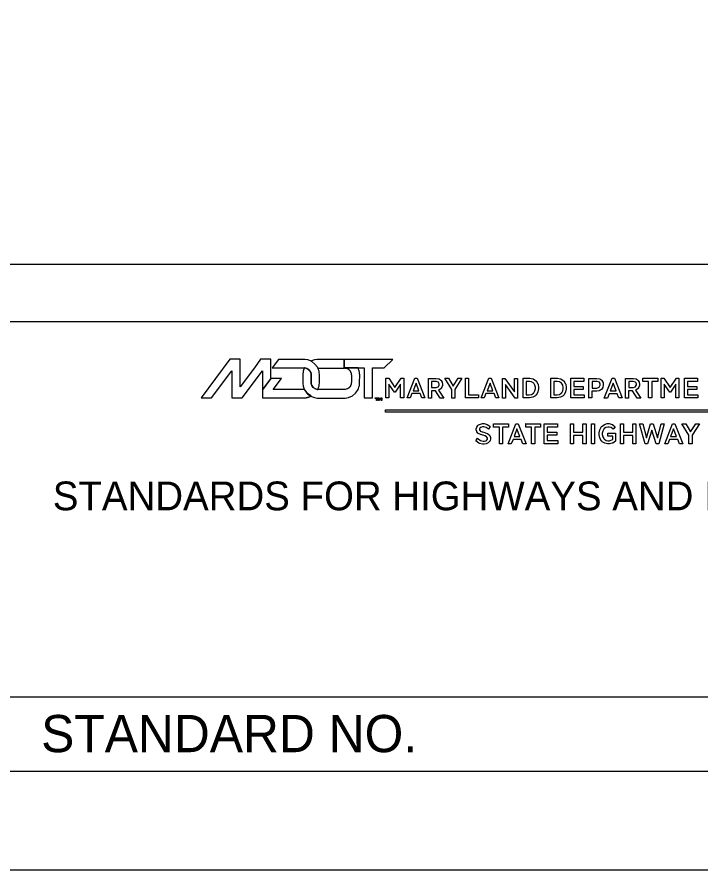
# Model space of a CAD drawing. Extents: x -0.5 to 19.9, y 5.2 to 17.3.
# Drawn here: x 15.428 to 17.634, y 5.667 to 8.417 of the extents above; entities that cross this region are included whole.
import ezdxf

# ---------------------------------------------------------------- set-up
doc = ezdxf.new("R2010")
doc.units = 0
for name, color, linetype in [('BORD-LINE', 7, 'Continuous'), ('MSHA-LOGO', 7, 'Continuous'), ('TTLB-TEXT', 7, 'Continuous'), ('USER-CLIP', 7, 'Continuous')]:
    doc.layers.add(name, color=color, linetype=linetype)

msp = doc.modelspace()

# ---------------------------------------------------------------- linework, layer by layer
at = {"layer": 'BORD-LINE'}
for p, q in [((19.6208, 7.6193), (12.2466, 7.6193)), ((19.6208, 7.4352), (15.1479, 7.4352)), ((15.1479, 6.2262), (19.6208, 6.2262))]:
    msp.add_line(p, q, dxfattribs=at)
msp.add_lwpolyline([(12.2466, 16.3375), (19.6208, 16.3375), (19.6208, 5.9844), (12.2466, 5.9844)], close=True, dxfattribs=at)
at = {"layer": 'MSHA-LOGO'}
for points in [[(16.2199, 7.2152), (16.247, 7.2513), (16.247, 7.314), (16.214, 7.314), (16.1936, 7.2866), (16.1478, 7.2255), (16.1478, 7.314), (16.1148, 7.314), (16.0216, 7.1897), (16.0556, 7.1897), (16.1206, 7.2765), (16.1206, 7.1897), (16.1548, 7.1897), (16.2199, 7.2765)], [(16.355, 7.2861), (16.3558, 7.2861), (16.3634, 7.2841), (16.3641, 7.2837), (16.365, 7.2833), (16.3687, 7.2805), (16.3719, 7.2772), (16.3725, 7.2765), (16.3731, 7.2756), (16.3753, 7.2709), (16.3765, 7.2658), (16.3766, 7.2648), (16.3766, 7.2648), (16.3766, 7.2646), (16.3766, 7.2646), (16.3766, 7.2643), (16.3766, 7.2637), (16.3766, 7.2635), (16.3766, 7.24), (16.3766, 7.2397), (16.3766, 7.2391), (16.3766, 7.2389), (16.3766, 7.2389), (16.3766, 7.2387), (16.3766, 7.2387), (16.3766, 7.2382), (16.3765, 7.2371), (16.3765, 7.2367), (16.3767, 7.2347), (16.3789, 7.2291), (16.3837, 7.2229), (16.3904, 7.2184), (16.3965, 7.2165), (16.3979, 7.2164), (16.3981, 7.2168), (16.3983, 7.217), (16.3983, 7.217), (16.3985, 7.2175), (16.4005, 7.2219), (16.4007, 7.2224), (16.4008, 7.2229), (16.4023, 7.2276), (16.4024, 7.2281), (16.4024, 7.2283), (16.403, 7.2307), (16.4031, 7.231), (16.4032, 7.2317), (16.4039, 7.238), (16.4039, 7.2401), (16.4039, 7.2632), (16.4039, 7.2655), (16.4032, 7.2716), (16.4031, 7.2723), (16.403, 7.2726), (16.4025, 7.275), (16.4024, 7.2753), (16.4023, 7.2757), (16.4008, 7.2805), (16.4007, 7.2809), (16.4005, 7.2814), (16.3985, 7.2859), (16.3983, 7.2863), (16.3971, 7.2886), (16.3891, 7.2988), (16.3789, 7.3068), (16.3766, 7.308), (16.3749, 7.3089), (16.3657, 7.3121), (16.3568, 7.3135), (16.3538, 7.3135), (16.2719, 7.3135), (16.2515, 7.2863), (16.3538, 7.2863), (16.3539, 7.2862), (16.3547, 7.2861)], [(16.3984, 7.2859), (16.3989, 7.2859), (16.3991, 7.2859), (16.4831, 7.2859), (16.4832, 7.2859), (16.4835, 7.2859), (16.4836, 7.2859), (16.4838, 7.2863), (16.4838, 7.3133), (16.4837, 7.3133), (16.4832, 7.3133), (16.4831, 7.3133), (16.3991, 7.3133), (16.3961, 7.3133), (16.3872, 7.3119), (16.378, 7.3087), (16.3766, 7.308), (16.3789, 7.3068), (16.3891, 7.2988), (16.3971, 7.2886), (16.3983, 7.2863)], [(16.4838, 7.3133), (16.4838, 7.2861), (16.5481, 7.2861), (16.5481, 7.1897), (16.5751, 7.1897), (16.5751, 7.2861), (16.6127, 7.2861), (16.6397, 7.3131), (16.6397, 7.3133)], [(16.3771, 7.1952), (16.3771, 7.1952), (16.3768, 7.1953), (16.3768, 7.1954), (16.3756, 7.196), (16.3653, 7.2035), (16.3644, 7.2045), (16.3635, 7.2054), (16.3561, 7.2156), (16.3555, 7.2167), (16.3554, 7.2167), (16.3551, 7.2167), (16.355, 7.2167), (16.3547, 7.2167), (16.354, 7.2167), (16.3538, 7.2167), (16.2544, 7.2167), (16.2808, 7.2517), (16.2468, 7.2517), (16.2197, 7.2157), (16.2197, 7.1895), (16.3536, 7.1895), (16.3544, 7.1895), (16.3565, 7.1896), (16.3567, 7.1897), (16.3574, 7.1897), (16.3594, 7.19), (16.3596, 7.19), (16.3598, 7.19), (16.3603, 7.1902), (16.3605, 7.1902), (16.3607, 7.1902), (16.3622, 7.1905), (16.3624, 7.1905), (16.3626, 7.1905), (16.3632, 7.1907), (16.3634, 7.1907), (16.3635, 7.1908), (16.365, 7.191), (16.3651, 7.191), (16.3652, 7.1911), (16.3661, 7.1914), (16.3662, 7.1914), (16.3663, 7.1914), (16.3676, 7.1919), (16.3677, 7.1919), (16.3678, 7.192), (16.3686, 7.1922), (16.3687, 7.1922), (16.3689, 7.1923), (16.3701, 7.1927), (16.3703, 7.1928), (16.3704, 7.1928), (16.3712, 7.1931), (16.3713, 7.1931), (16.3714, 7.1932), (16.3729, 7.1938), (16.373, 7.1938), (16.3731, 7.1938), (16.3738, 7.1941), (16.3739, 7.1942), (16.3741, 7.1942), (16.3761, 7.1952), (16.3763, 7.1954), (16.3764, 7.1953), (16.377, 7.1952)], [(16.6179, 7.2528), (16.6268, 7.2528), (16.6471, 7.2232), (16.6667, 7.2528), (16.6752, 7.2528), (16.6752, 7.1893), (16.6654, 7.1893), (16.6654, 7.2334), (16.6481, 7.2081), (16.6454, 7.2081), (16.6278, 7.2334), (16.6278, 7.1893), (16.6179, 7.1893)], [(16.7115, 7.2528), (16.7191, 7.2528), (16.7439, 7.1893), (16.7335, 7.1893), (16.7279, 7.2035), (16.702, 7.2035), (16.6965, 7.1893), (16.6863, 7.1893)], [(16.706, 7.2127), (16.7246, 7.2127), (16.7151, 7.2367)], [(16.7554, 7.189), (16.7554, 7.2525), (16.7776, 7.2525), (16.7804, 7.2525), (16.788, 7.2511), (16.7888, 7.2508), (16.7895, 7.2506), (16.7952, 7.2467), (16.7956, 7.2462), (16.796, 7.2457), (16.799, 7.2405), (16.7992, 7.24), (16.7994, 7.2394), (16.8002, 7.2342), (16.8002, 7.2324), (16.8002, 7.2295), (16.7975, 7.2217), (16.797, 7.2209), (16.7964, 7.2201), (16.7888, 7.2143), (16.7878, 7.214), (16.8048, 7.1886), (16.7927, 7.1886), (16.7773, 7.212), (16.7652, 7.212), (16.7652, 7.1886), (16.7554, 7.1886)], [(16.7652, 7.2423), (16.7652, 7.2229), (16.778, 7.2229), (16.7802, 7.2229), (16.7862, 7.2251), (16.7868, 7.2255), (16.7873, 7.2259), (16.7901, 7.2313), (16.7901, 7.2331), (16.7901, 7.2348), (16.7876, 7.2396), (16.7871, 7.24), (16.7866, 7.2404), (16.7799, 7.2423), (16.7776, 7.2423)], [(16.8401, 7.2166), (16.8401, 7.189), (16.8303, 7.189), (16.8303, 7.2166), (16.8074, 7.2528), (16.8195, 7.2528), (16.8352, 7.2275), (16.8513, 7.2528), (16.8631, 7.2528)], [(16.8742, 7.2528), (16.884, 7.2528), (16.884, 7.1995), (16.9164, 7.1995), (16.9164, 7.1893), (16.8742, 7.1893)], [(16.9501, 7.2528), (16.9576, 7.2528), (16.9825, 7.1893), (16.972, 7.1893), (16.9665, 7.2035), (16.9406, 7.2035), (16.935, 7.1893), (16.9252, 7.1893)], [(16.9445, 7.2127), (16.9632, 7.2127), (16.9537, 7.2367)], [(17.0349, 7.189), (17.0034, 7.2324), (17.0034, 7.189), (16.994, 7.189), (16.994, 7.2525), (17.0015, 7.2525), (17.0329, 7.2091), (17.0329, 7.2525), (17.0424, 7.2525), (17.0424, 7.189)], [(17.0604, 7.2528), (17.078, 7.2528), (17.0818, 7.2528), (17.092, 7.2509), (17.0931, 7.2505), (17.0942, 7.2501), (17.1026, 7.2443), (17.1033, 7.2436), (17.1038, 7.2429), (17.1082, 7.2346), (17.1085, 7.2337), (17.1087, 7.2328), (17.1101, 7.2246), (17.1101, 7.2219), (17.1101, 7.2186), (17.1081, 7.2088), (17.1033, 7.1998), (17.1019, 7.1982), (17.1005, 7.1967), (17.0916, 7.1915), (17.0807, 7.1893), (17.0771, 7.1893), (17.0604, 7.1893)], [(17.0702, 7.2423), (17.0702, 7.1995), (17.0777, 7.1995), (17.0802, 7.1995), (17.0875, 7.201), (17.0935, 7.2044), (17.0944, 7.2054), (17.0953, 7.2064), (17.0986, 7.2125), (17.1, 7.2195), (17.1, 7.2219), (17.1, 7.2242), (17.0986, 7.231), (17.0945, 7.2374), (17.0877, 7.2413), (17.0805, 7.2426), (17.078, 7.2426), (17.0702, 7.2426)], [(17.1497, 7.2528), (17.1674, 7.2528), (17.1711, 7.2528), (17.1814, 7.2509), (17.1824, 7.2505), (17.1835, 7.2501), (17.1919, 7.2443), (17.1926, 7.2436), (17.1931, 7.2429), (17.1976, 7.2346), (17.1978, 7.2337), (17.1981, 7.2328), (17.1995, 7.2246), (17.1995, 7.2219), (17.1995, 7.2186), (17.1975, 7.2088), (17.1927, 7.1998), (17.1913, 7.1982), (17.1899, 7.1967), (17.1809, 7.1915), (17.17, 7.1893), (17.1664, 7.1893), (17.1497, 7.1893)], [(17.1599, 7.2423), (17.1599, 7.1995), (17.1674, 7.1995), (17.1699, 7.1995), (17.1772, 7.201), (17.1832, 7.2044), (17.1841, 7.2054), (17.185, 7.2064), (17.1882, 7.2125), (17.1897, 7.2195), (17.1897, 7.2219), (17.1897, 7.2242), (17.1883, 7.231), (17.1842, 7.2374), (17.1773, 7.2413), (17.1701, 7.2426), (17.1677, 7.2426), (17.1599, 7.2426)], [(17.2142, 7.2528), (17.2564, 7.2528), (17.2564, 7.2426), (17.224, 7.2426), (17.224, 7.2265), (17.2544, 7.2265), (17.2544, 7.2166), (17.224, 7.2166), (17.224, 7.1998), (17.2574, 7.1998), (17.2574, 7.1896), (17.2142, 7.1896)], [(17.2724, 7.189), (17.2724, 7.2525), (17.2953, 7.2525), (17.2983, 7.2525), (17.3063, 7.2511), (17.3071, 7.2508), (17.3079, 7.2505), (17.3139, 7.2464), (17.3143, 7.2459), (17.3147, 7.2454), (17.3178, 7.2399), (17.3179, 7.2393), (17.3181, 7.2387), (17.3189, 7.2335), (17.3189, 7.2317), (17.3189, 7.2299), (17.3178, 7.2248), (17.3176, 7.2242), (17.3174, 7.2236), (17.3141, 7.2181), (17.3137, 7.2176), (17.3133, 7.2171), (17.307, 7.213), (17.3062, 7.2127), (17.3053, 7.2123), (17.2976, 7.211), (17.295, 7.211), (17.2819, 7.211), (17.2819, 7.1893), (17.2724, 7.1893)], [(17.2826, 7.2426), (17.2826, 7.2212), (17.2957, 7.2212), (17.2982, 7.2212), (17.306, 7.2239), (17.3094, 7.2301), (17.3094, 7.2321), (17.3094, 7.2341), (17.3062, 7.2399), (17.2988, 7.2426), (17.2963, 7.2426)], [(17.3474, 7.2528), (17.3549, 7.2528), (17.3798, 7.1893), (17.3693, 7.1893), (17.3637, 7.2031), (17.3379, 7.2031), (17.3323, 7.189), (17.3222, 7.189)], [(17.3415, 7.2127), (17.3602, 7.2127), (17.3507, 7.2367)], [(17.3909, 7.189), (17.3909, 7.2525), (17.4132, 7.2525), (17.4159, 7.2525), (17.4235, 7.2511), (17.4243, 7.2508), (17.425, 7.2506), (17.4307, 7.2467), (17.4312, 7.2462), (17.4316, 7.2457), (17.4345, 7.2405), (17.4348, 7.24), (17.4349, 7.2394), (17.4357, 7.2342), (17.4357, 7.2324), (17.4357, 7.2295), (17.433, 7.2217), (17.4325, 7.2209), (17.4319, 7.2201), (17.4243, 7.2143), (17.4233, 7.214), (17.4403, 7.1886), (17.4282, 7.1886), (17.4128, 7.212), (17.4007, 7.212), (17.4007, 7.1886), (17.3909, 7.1886)], [(17.4011, 7.2423), (17.4011, 7.2229), (17.4138, 7.2229), (17.416, 7.2229), (17.4221, 7.2251), (17.4227, 7.2255), (17.4231, 7.2259), (17.4259, 7.2313), (17.4259, 7.2331), (17.4259, 7.2348), (17.4235, 7.2396), (17.423, 7.24), (17.4225, 7.2404), (17.4157, 7.2423), (17.4135, 7.2423)], [(17.4462, 7.2528), (17.4943, 7.2528), (17.4943, 7.2426), (17.475, 7.2426), (17.475, 7.1893), (17.4652, 7.1893), (17.4652, 7.2426), (17.4462, 7.2426)], [(17.5058, 7.2528), (17.5146, 7.2528), (17.5349, 7.2232), (17.5545, 7.2528), (17.563, 7.2528), (17.563, 7.1893), (17.5532, 7.1893), (17.5532, 7.2334), (17.5359, 7.2081), (17.5333, 7.2081), (17.5156, 7.2334), (17.5156, 7.1893), (17.5058, 7.1893)], [(17.5807, 7.2528), (17.6229, 7.2528), (17.6229, 7.2426), (17.5905, 7.2426), (17.5905, 7.2265), (17.621, 7.2265), (17.621, 7.2166), (17.5905, 7.2166), (17.5905, 7.1998), (17.6239, 7.1998), (17.6239, 7.1896), (17.5807, 7.1896)], [(16.5837, 7.1897), (16.5926, 7.1897), (16.5926, 7.1881), (16.5892, 7.1881), (16.5892, 7.1807), (16.5874, 7.1807), (16.5874, 7.1881), (16.5837, 7.1881)], [(16.5938, 7.1897), (16.5955, 7.1897), (16.5993, 7.1853), (16.603, 7.1897), (16.6046, 7.1897), (16.6046, 7.1807), (16.6025, 7.1807), (16.6025, 7.1871), (16.5991, 7.183), (16.5957, 7.1871), (16.5957, 7.1807), (16.5938, 7.1807)], [(16.617, 7.151), (18.7337, 7.151), (18.7337, 7.1432), (16.617, 7.1432)], [(16.9431, 7.0638), (16.9428, 7.0641), (16.9385, 7.0667), (16.938, 7.067), (16.9374, 7.0671), (16.9316, 7.0691), (16.931, 7.0692), (16.9303, 7.0694), (16.9239, 7.0712), (16.9233, 7.0715), (16.9227, 7.0717), (16.9168, 7.0744), (16.9163, 7.0747), (16.9157, 7.075), (16.9115, 7.0796), (16.9112, 7.0801), (16.9108, 7.0807), (16.9092, 7.0866), (16.9092, 7.0885), (16.9092, 7.0902), (16.9109, 7.0955), (16.9146, 7.1005), (16.9156, 7.1013), (16.9167, 7.1022), (16.9228, 7.1052), (16.9296, 7.1065), (16.9319, 7.1065), (16.9351, 7.1065), (16.9447, 7.1041), (16.9529, 7.0987), (16.9543, 7.0972), (16.9489, 7.0891), (16.9477, 7.0903), (16.9409, 7.0942), (16.9339, 7.0959), (16.9316, 7.0959), (16.9294, 7.0959), (16.9235, 7.0943), (16.923, 7.0939), (16.9224, 7.0936), (16.9195, 7.0895), (16.9195, 7.0882), (16.9195, 7.0869), (16.9216, 7.0834), (16.922, 7.083), (16.9224, 7.0827), (16.928, 7.0803), (16.9287, 7.0801), (16.9294, 7.08), (16.9365, 7.0778), (16.9373, 7.0776), (16.9381, 7.0773), (16.9453, 7.0746), (16.946, 7.0744), (16.9466, 7.074), (16.9522, 7.0692), (16.9527, 7.0686), (16.9531, 7.0679), (16.9553, 7.0614), (16.9553, 7.0593), (16.9553, 7.0574), (16.9536, 7.0516), (16.9499, 7.0463), (16.9489, 7.0455), (16.9478, 7.0446), (16.9417, 7.0414), (16.9353, 7.04), (16.9332, 7.04), (16.9295, 7.04), (16.9197, 7.0427), (16.9185, 7.0432), (16.9173, 7.0438), (16.9083, 7.0508), (16.9076, 7.0516), (16.9137, 7.0593), (16.915, 7.0578), (16.9226, 7.0523), (16.9313, 7.05), (16.9342, 7.05), (16.9361, 7.05), (16.9417, 7.0516), (16.9421, 7.0519), (16.9426, 7.0522), (16.945, 7.0563), (16.945, 7.0577), (16.945, 7.0592), (16.9434, 7.0634)], [(16.9645, 7.1055), (17.0131, 7.1055), (17.0131, 7.0949), (16.9939, 7.0949), (16.9939, 7.0413), (16.984, 7.0413), (16.984, 7.0952), (16.9648, 7.0952), (16.9648, 7.1055)], [(17.037, 7.1055), (17.0447, 7.1055), (17.0699, 7.0413), (17.0594, 7.0413), (17.054, 7.0554), (17.0278, 7.0554), (17.0223, 7.0413), (17.0121, 7.0413)], [(17.0683, 7.1055), (17.1169, 7.1055), (17.1169, 7.0949), (17.0977, 7.0949), (17.0977, 7.0413), (17.0879, 7.0413), (17.0879, 7.0952), (17.0687, 7.0952), (17.0687, 7.1055)], [(17.1284, 7.1055), (17.1712, 7.1055), (17.1712, 7.0949), (17.1383, 7.0949), (17.1383, 7.0789), (17.169, 7.0789), (17.169, 7.0689), (17.1383, 7.0689), (17.1383, 7.0519), (17.1719, 7.0519), (17.1719, 7.0413), (17.1284, 7.0413)], [(17.2533, 7.0686), (17.2233, 7.0686), (17.2233, 7.0413), (17.2134, 7.0413), (17.2134, 7.1055), (17.2233, 7.1055), (17.2233, 7.0789), (17.2533, 7.0789), (17.2533, 7.1055), (17.2632, 7.1055), (17.2632, 7.0413), (17.2533, 7.0413)], [(17.2808, 7.1055), (17.2907, 7.1055), (17.2907, 7.0413), (17.2808, 7.0413)], [(17.3339, 7.0756), (17.3588, 7.0756), (17.3588, 7.0509), (17.3581, 7.0501), (17.3498, 7.0439), (17.3489, 7.0435), (17.3478, 7.0431), (17.339, 7.041), (17.3361, 7.041), (17.333, 7.041), (17.3239, 7.0432), (17.3155, 7.0484), (17.314, 7.05), (17.3126, 7.0515), (17.3076, 7.0604), (17.3054, 7.0704), (17.3054, 7.0737), (17.3054, 7.0769), (17.3075, 7.0865), (17.3124, 7.0956), (17.3137, 7.0972), (17.3152, 7.0988), (17.3233, 7.1042), (17.3319, 7.1065), (17.3348, 7.1065), (17.3382, 7.1065), (17.3472, 7.1041), (17.3482, 7.1036), (17.3492, 7.1031), (17.3569, 7.0967), (17.3575, 7.0959), (17.3508, 7.0888), (17.3499, 7.0899), (17.3443, 7.0939), (17.3377, 7.0956), (17.3355, 7.0956), (17.3334, 7.0956), (17.3273, 7.0941), (17.322, 7.0905), (17.3211, 7.0894), (17.3202, 7.0885), (17.317, 7.0825), (17.3156, 7.0757), (17.3156, 7.0734), (17.3156, 7.0711), (17.3171, 7.0641), (17.3204, 7.0581), (17.3214, 7.057), (17.3224, 7.0561), (17.3279, 7.0527), (17.334, 7.0512), (17.3361, 7.0512), (17.3394, 7.0512), (17.3483, 7.055), (17.3492, 7.0557), (17.3492, 7.0657), (17.3339, 7.0657)], [(17.4144, 7.0686), (17.3843, 7.0686), (17.3843, 7.0413), (17.3744, 7.0413), (17.3744, 7.1055), (17.3843, 7.1055), (17.3843, 7.0789), (17.4144, 7.0789), (17.4144, 7.1055), (17.4243, 7.1055), (17.4243, 7.0413), (17.4144, 7.0413)], [(17.4981, 7.0413), (17.4898, 7.0413), (17.4757, 7.0859), (17.462, 7.0413), (17.4537, 7.0413), (17.4358, 7.1055), (17.446, 7.1055), (17.4581, 7.0612), (17.4716, 7.1055), (17.4796, 7.1055), (17.4933, 7.0612), (17.5051, 7.1055), (17.515, 7.1055)], [(17.5422, 7.1055), (17.5499, 7.1055), (17.5751, 7.0413), (17.5646, 7.0413), (17.5588, 7.0554), (17.5326, 7.0554), (17.5272, 7.0413), (17.5169, 7.0413)], [(17.6051, 7.0692), (17.6051, 7.0413), (17.5952, 7.0413), (17.5952, 7.0692), (17.5722, 7.1055), (17.5847, 7.1055), (17.6007, 7.0798), (17.617, 7.1055), (17.6288, 7.1055)], [(17.0313, 7.065), (17.0501, 7.065), (17.0406, 7.0894)], [(17.5361, 7.065), (17.555, 7.065), (17.5454, 7.0894)]]:
    msp.add_lwpolyline(points, close=True, dxfattribs=at)
for points in [[(16.3766, 7.2503), (16.3766, 7.2632), (16.3766, 7.2636), (16.3766, 7.2643), (16.3766, 7.2646), (16.3766, 7.2651), (16.3768, 7.2663), (16.3768, 7.2667), (16.3767, 7.2676), (16.3734, 7.2759), (16.3729, 7.2766), (16.3723, 7.2774), (16.369, 7.2809), (16.3651, 7.2836), (16.3643, 7.284), (16.3635, 7.2844), (16.356, 7.2864), (16.3552, 7.2865), (16.3552, 7.2864), (16.355, 7.2861), (16.3546, 7.2855), (16.352, 7.2787), (16.3517, 7.278), (16.3516, 7.2778), (16.351, 7.2754), (16.3509, 7.2751), (16.3507, 7.2741), (16.3495, 7.2659), (16.3495, 7.2632), (16.3495, 7.2503), (16.3495, 7.2489)], [(16.3495, 7.2489), (16.3495, 7.2393), (16.3495, 7.2363), (16.351, 7.2273), (16.3541, 7.2181), (16.355, 7.2164), (16.3556, 7.2152), (16.3632, 7.2047), (16.3641, 7.2038), (16.365, 7.2029), (16.3755, 7.1953), (16.3766, 7.1947), (16.3784, 7.1938), (16.3875, 7.1906), (16.3965, 7.1892), (16.3995, 7.1892), (16.4834, 7.1892), (16.4869, 7.1892), (16.4974, 7.1911), (16.5098, 7.1967), (16.5201, 7.2053), (16.5263, 7.2134), (16.5279, 7.2164), (16.528, 7.2166), (16.529, 7.2187), (16.5291, 7.2189), (16.5293, 7.2194), (16.5308, 7.2237), (16.531, 7.2241), (16.5311, 7.2244), (16.5318, 7.227), (16.5318, 7.2272), (16.5318, 7.2274), (16.5318, 7.2276), (16.5319, 7.2277), (16.5323, 7.2296), (16.5324, 7.2298), (16.5324, 7.23), (16.5325, 7.2304), (16.5325, 7.2305), (16.5326, 7.2307), (16.5328, 7.2324), (16.5329, 7.2325), (16.5329, 7.2326), (16.5329, 7.2328), (16.5329, 7.2329), (16.5329, 7.233), (16.5329, 7.2333), (16.5329, 7.2334), (16.5329, 7.2339), (16.533, 7.2351), (16.533, 7.2355), (16.533, 7.2362), (16.533, 7.2363), (16.533, 7.2371), (16.5332, 7.2387), (16.5332, 7.2393), (16.5334, 7.2632)], [(16.5334, 7.2632), (16.5334, 7.2639), (16.5333, 7.2659), (16.5332, 7.2661), (16.5332, 7.2663), (16.5332, 7.267), (16.5332, 7.2675), (16.533, 7.2687), (16.533, 7.2691), (16.533, 7.2692), (16.533, 7.2695), (16.533, 7.2696), (16.533, 7.2697), (16.533, 7.2699), (16.533, 7.2699), (16.533, 7.2701), (16.5327, 7.2718), (16.5327, 7.272), (16.5327, 7.2722), (16.5325, 7.2726), (16.5325, 7.2727), (16.5325, 7.2729), (16.5321, 7.2747), (16.532, 7.2749), (16.532, 7.2751), (16.532, 7.2753), (16.5319, 7.2755), (16.5312, 7.2781), (16.5312, 7.2784), (16.531, 7.2788), (16.5294, 7.2831), (16.5293, 7.2835), (16.5292, 7.2837), (16.5281, 7.2859), (16.5281, 7.2861), (16.5281, 7.2862), (16.5279, 7.2865), (16.4845, 7.2865), (16.4843, 7.2861), (16.4848, 7.2861), (16.485, 7.2861), (16.4852, 7.2861), (16.4857, 7.286), (16.4858, 7.2859), (16.4862, 7.2859), (16.4896, 7.2852), (16.49, 7.2851), (16.4902, 7.285), (16.4931, 7.284), (16.4934, 7.2839), (16.4936, 7.2838), (16.4951, 7.2829), (16.4953, 7.2828), (16.4954, 7.2828), (16.4954, 7.2828), (16.4956, 7.2828), (16.497, 7.2819), (16.4972, 7.2818), (16.4973, 7.2817), (16.4973, 7.2816), (16.4975, 7.2815), (16.4987, 7.2806), (16.4989, 7.2804), (16.499, 7.2803), (16.4992, 7.2802), (16.5002, 7.2791), (16.5003, 7.279), (16.5004, 7.2789), (16.5004, 7.2789), (16.5006, 7.2787), (16.5007, 7.2786), (16.5014, 7.2778), (16.5015, 7.2777), (16.5016, 7.2775), (16.5017, 7.2775), (16.5019, 7.277), (16.502, 7.277), (16.5021, 7.2769), (16.5028, 7.2759), (16.5028, 7.2758), (16.5029, 7.2757), (16.5031, 7.2752), (16.5032, 7.2751), (16.5033, 7.2749), (16.5033, 7.2749), (16.5034, 7.2748), (16.5038, 7.274), (16.5039, 7.2739), (16.5039, 7.2738), (16.5042, 7.2731), (16.5042, 7.273), (16.5042, 7.2729), (16.5047, 7.2719), (16.5047, 7.2718), (16.5048, 7.2718), (16.5049, 7.2711), (16.5049, 7.271), (16.505, 7.2708), (16.5051, 7.2708), (16.5051, 7.2707), (16.5054, 7.27), (16.5054, 7.2697), (16.5054, 7.2697), (16.5057, 7.2686), (16.5057, 7.2685), (16.5057, 7.2683), (16.5059, 7.2677), (16.5059, 7.2675), (16.506, 7.2674), (16.5061, 7.2664), (16.5061, 7.2661), (16.5061, 7.2659), (16.5063, 7.2654), (16.5063, 7.2653), (16.5063, 7.2647), (16.5064, 7.2635), (16.5064, 7.263), (16.5064, 7.2394), (16.5064, 7.2389), (16.5063, 7.2374), (16.5063, 7.2372), (16.5063, 7.237), (16.5061, 7.2364), (16.5061, 7.2363), (16.5061, 7.236), (16.5059, 7.2352), (16.5059, 7.235), (16.5059, 7.2347), (16.5057, 7.2341), (16.5057, 7.2339), (16.5057, 7.2338), (16.5054, 7.2328), (16.5054, 7.2327), (16.5054, 7.2326), (16.5051, 7.2318), (16.5051, 7.2317), (16.5051, 7.2316), (16.5049, 7.2314), (16.5049, 7.2313), (16.5047, 7.2308), (16.5047, 7.2307), (16.5047, 7.2306), (16.5042, 7.2296), (16.5042, 7.2295), (16.5042, 7.2294), (16.5039, 7.2287), (16.5039, 7.2286), (16.5038, 7.2285), (16.5034, 7.2276), (16.5033, 7.2276), (16.5032, 7.2274), (16.5032, 7.2274), (16.5031, 7.2273), (16.5029, 7.2268), (16.5028, 7.2267), (16.5027, 7.2266), (16.5021, 7.2256), (16.502, 7.2255), (16.5019, 7.2255), (16.5017, 7.225), (16.5016, 7.225), (16.5015, 7.2248), (16.5014, 7.2247), (16.5006, 7.2239), (16.5006, 7.2238), (16.5004, 7.2236), (16.5003, 7.2234), (16.5003, 7.2234), (16.5002, 7.2233), (16.4991, 7.2223), (16.499, 7.2222), (16.4989, 7.222), (16.4987, 7.222), (16.4975, 7.2209), (16.4973, 7.2208), (16.4972, 7.2207), (16.4972, 7.2207), (16.497, 7.2206), (16.4956, 7.2197), (16.4954, 7.2196), (16.4953, 7.2196), (16.4953, 7.2196), (16.4951, 7.2196), (16.4936, 7.2187), (16.4934, 7.2186), (16.4931, 7.2185), (16.4902, 7.2175), (16.49, 7.2174), (16.4896, 7.2173), (16.4862, 7.2166), (16.4858, 7.2165), (16.4856, 7.2165), (16.4851, 7.2164), (16.485, 7.2164), (16.4847, 7.2164), (16.484, 7.2164), (16.4838, 7.2164), (16.3998, 7.2164), (16.3995, 7.2164), (16.3988, 7.2164), (16.3986, 7.2164), (16.3965, 7.2165), (16.3904, 7.2184), (16.3837, 7.2231), (16.379, 7.2298), (16.3771, 7.2358), (16.377, 7.2379), (16.377, 7.2382), (16.377, 7.239), (16.377, 7.2393), (16.377, 7.2503), (16.3766, 7.2503)]]:
    msp.add_lwpolyline(points, dxfattribs=at)
at = {"layer": 'USER-CLIP'}
msp.add_lwpolyline([(19.9377, 16.6675), (11.4377, 16.6675), (11.4377, 5.6675), (19.9377, 5.6675)], close=True, dxfattribs=at)

# ---------------------------------------------------------------- texts
at = {"layer": 'TTLB-TEXT'}
for s, height, p in [('STANDARDS FOR HIGHWAYS AND INCIDENTAL STRUCTURES', 0.09269, (15.5437, 6.8272)), ('STANDARD NO.', 0.12, (15.5061, 6.0472))]:
    msp.add_text(s, height=height, dxfattribs=at).set_placement(p)

doc.saveas('drawing.dxf')
